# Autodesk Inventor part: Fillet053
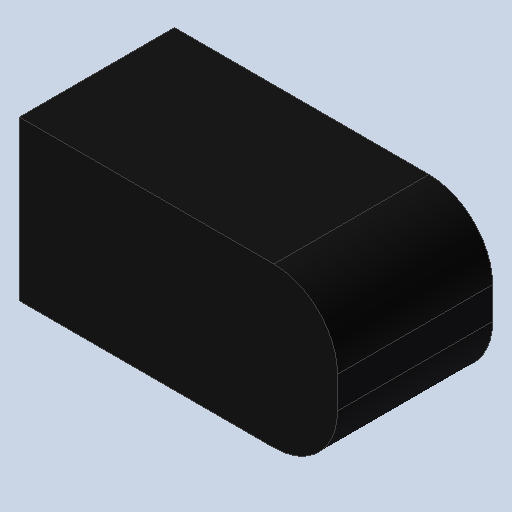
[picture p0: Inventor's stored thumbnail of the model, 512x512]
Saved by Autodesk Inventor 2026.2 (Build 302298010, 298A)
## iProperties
Created: 2026-10
Part Number: Fillet053
Material: Générique
Document SubType Name: Modeling
Designer: mel
Density: 1 g/cm^3
Appearance: Par défaut
Author: mel
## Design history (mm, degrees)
feature "Base1"
node "Solide1"
